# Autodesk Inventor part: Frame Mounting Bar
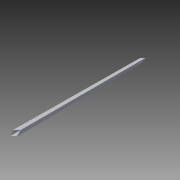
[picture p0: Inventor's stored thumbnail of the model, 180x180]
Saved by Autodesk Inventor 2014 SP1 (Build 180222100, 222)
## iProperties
Created: 2014-06
Part Number: Frame Mounting Bar
Material: Aluminum 6061
Document SubType Name: Modeling
Designer: Michael
Density: 2.71 g/cm^3
Appearance: Aluminum - Flat
Author: Michael
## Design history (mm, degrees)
sketch "Sketch3"
  geometry: L1 (-9.525, -9.525)-(9.525, -9.525); L2 (9.525, -9.525)-(9.525, 9.525); L3 (9.525, 9.525)-(-9.525, 9.525); L4 (-9.525, 9.525)-(-9.525, -9.525); L5 (-9.525, -9.525)-(9.525, 9.525); L6 (9.525, -9.525)-(-9.525, 9.525); L7 (-7.938, -7.938)-(7.938, -7.938); L8 (7.938, -7.938)-(7.938, 7.938); L9 (7.938, 7.938)-(-7.938, 7.938); L10 (-7.938, 7.938)-(-7.938, -7.938); L11 (-7.938, -7.938)-(7.938, 7.938); L12 (7.938, -7.938)-(-7.938, 7.938); 1 further point
  constraints: 24 end point, 4 midpoint, 4 parallel, 2 horizontal, 2 perpendicular, 1 point on line
  dimensions: "d8" = 19.05 distance of L3.end L2.end; "d9" = 19.05 distance between parallel lines of L1 L3 (= d8); "d10" = 1.5875 distance between parallel lines of L3 L9
extrude "Extrusion3" new body sketch "Sketch3" distance "d11" = 647.7; taper "d12" = 0 deg
body "Solid2"
